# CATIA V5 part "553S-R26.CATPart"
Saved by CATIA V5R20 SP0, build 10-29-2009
Part number: 553S-R26
Definition: NONE
Nomenclature: 553S-R26
Source: Unknown
Description: 553S-R26
Bounding box of the stored display mesh (mm): x -14.5 to 14.5, y -15.5 to 15.492, z -0.6 to 0.6
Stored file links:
  C:\Users\Utente\Desktop\IO LAVORO\3D X SITO CF\X SITO\PLASTICA\553S\553S-R26.CATPart
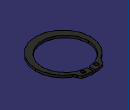
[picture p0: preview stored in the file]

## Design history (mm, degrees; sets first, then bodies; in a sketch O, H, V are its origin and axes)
Body1 "553S-R26" (main body)
  Solid1: solid without history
